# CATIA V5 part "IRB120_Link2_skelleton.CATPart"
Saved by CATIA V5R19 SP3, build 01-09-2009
Part number: IRB120_Link2_skelleton
Bounding box of the stored display mesh (mm): x 0 to 0, y 0 to 65, z 0 to 270
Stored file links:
  Z:\Projects\ABB_Robotics\ABB LIB\V5\V5PARTS\ABB\120\IRB120_Link2_skelleton.CATPart
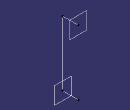
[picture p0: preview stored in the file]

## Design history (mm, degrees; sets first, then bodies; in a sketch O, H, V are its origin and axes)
Body1 (main body)
  Line1: type PtPt, FirstPoint {point type Coord, X 0, Y 0, Z 0}, SecondPoint {point type Coord, X 0, Y 0, Z 270, RefPoint {point type Coord, X 0, Y 0, Z 0}}
  Line2: type PtPt, FirstPoint vertex of Line1, SecondPoint {point type Coord, X 0, Y 65, Z 0, RefPoint vertex of Line1}
  Line3: type PtPt, FirstPoint vertex of Line1, SecondPoint {point type Coord, X 0, Y 65, Z 0, RefPoint vertex of Line1}
  Plane1: type OffsetPt, RefPlane zx-plane, RefPoint vertex of Line3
